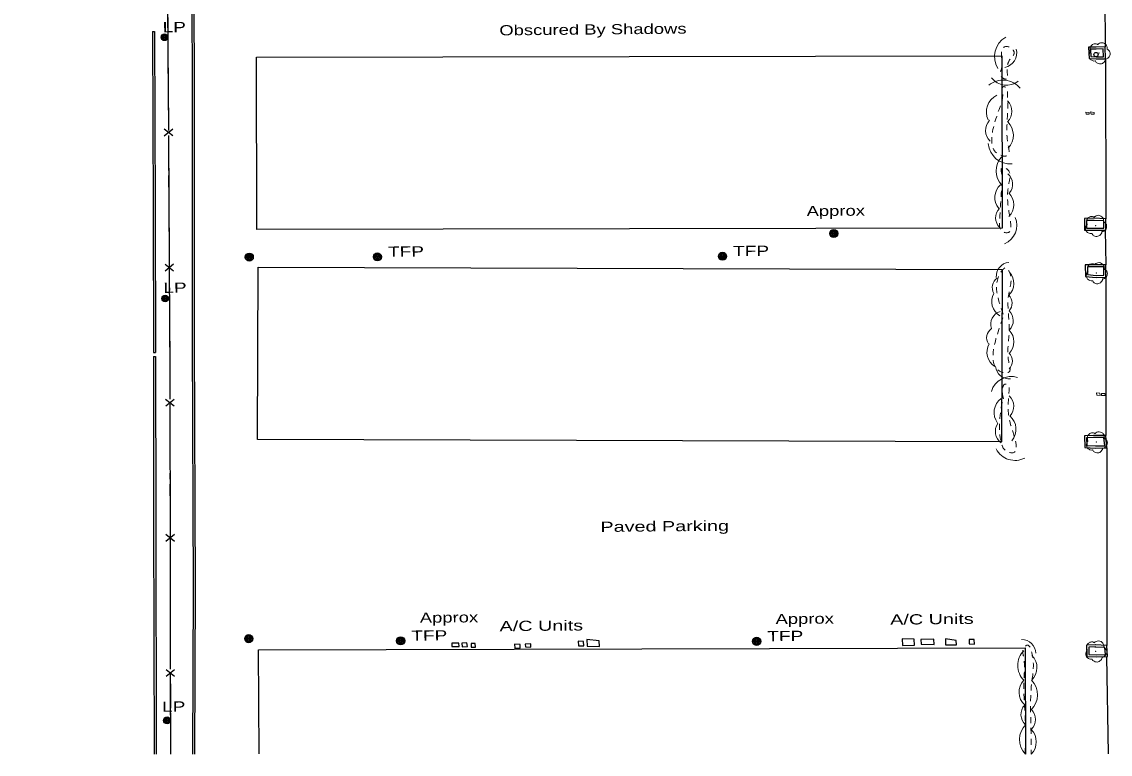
# Model space of a CAD drawing. Extents: x 2362213 to 2366494, y 6968794 to 6978110.
# Drawn here: x 2362436 to 2362949, y 6975890 to 6976234 of the extents above; entities that cross this region are included whole.
import ezdxf

# ---------------------------------------------------------------- set-up
doc = ezdxf.new("R2010")
doc.units = 0
doc.header["$LTSCALE"] = 1.9
doc.linetypes.add('LONG_DASH_SHORT_DASH', pattern=[9.9, 6, -1.2, 1.5, -1.2])
doc.linetypes.add('SHORT_DASHED', pattern=[2.7, 1.5, -1.2])
for name, color, linetype, lineweight in [('11', 7, 'Continuous', 25), ('17', 7, 'Continuous', 25), ('2', 7, 'Continuous', 25), ('20', 7, 'Continuous', 25), ('23', 7, 'Continuous', 25), ('29', 7, 'Continuous', 13), ('9', 7, 'Continuous', 13)]:
    doc.layers.add(name, color=color, linetype=linetype, lineweight=lineweight)

msp = doc.modelspace()

# ---------------------------------------------------------------- linework, layer by layer
at = {"layer": '11'}
for points in [[(2362546.8, 6976217.851), (2362897.792, 6976218.433), (2362897.925, 6976137.251), (2362546.933, 6976136.679)], [(2362547.593, 6976118.894), (2362897.85, 6976117.819), (2362897.601, 6976036.822), (2362547.344, 6976037.897)]]:
    msp.add_lwpolyline(points, close=True, dxfattribs=at)
msp.add_lwpolyline([(2362548.043, 6975889.887), (2362547.757, 6975938.867), (2362908.765, 6975939.844), (2362908.962, 6975889.735)], dxfattribs=at)
at = {"layer": '17'}
for p, q in [((2362503.4, 6976184.036), (2362507.411, 6976180.864)), ((2362503.411, 6976180.836), (2362507.4, 6976184.064)), ((2362505.393, 6976180.645), (2362505.744, 6976120.646)), ((2362503.776, 6976120.437), (2362507.797, 6976117.265)), ((2362503.797, 6976117.237), (2362507.777, 6976120.465)), ((2362504.082, 6976056.846), (2362508.093, 6976053.654)), ((2362504.092, 6976053.646), (2362508.083, 6976056.854)), ((2362506.054, 6976053.445), (2362506.155, 6975993.443)), ((2362504.197, 6975993.244), (2362508.199, 6975990.052)), ((2362504.198, 6975990.044), (2362508.198, 6975993.252)), ((2362506.16, 6975989.843), (2362506.271, 6975929.842)), ((2362504.303, 6975929.643), (2362508.314, 6975926.45)), ((2362504.313, 6975926.442), (2362508.304, 6975929.652)), ((2362506.275, 6975926.241), (2362506.343, 6975889.77))]:
    msp.add_line(p, q, dxfattribs=at)
at = {"layer": '17', "linetype": 'LONG_DASH_SHORT_DASH'}
msp.add_lwpolyline([(2362436.337, 6976448.61), (2362504.849, 6976448.732), (2362504.318, 6976368.123), (2362505.162, 6976218.565), (2362506.025, 6976073.326), (2362506.343, 6975889.77)], dxfattribs=at)
at = {"layer": '17'}
for points in [[(2362505.017, 6976244.244), (2362505.162, 6976218.565), (2362505.369, 6976184.245)], [(2362505.768, 6976117.046), (2362506.025, 6976073.326), (2362506.05, 6976057.045)]]:
    msp.add_lwpolyline(points, dxfattribs=at)
at = {"layer": '2'}
for p, q in [((2362945.945, 6976312.786), (2362946.463, 6976222.697)), ((2362497.914, 6976229.806), (2362498.874, 6976229.805)), ((2362946.578, 6976216.989), (2362946.745, 6976141.646)), ((2362946.476, 6976136.353), (2362946.771, 6976120.005)), ((2362946.776, 6976114.225), (2362946.686, 6976039.711)), ((2362498.302, 6976078.812), (2362499.262, 6976078.811)), ((2362498.41, 6976076.933), (2362499.37, 6976076.912)), ((2362947.251, 6976033.915), (2362947.167, 6975940.89)), ((2362947.117, 6975935.66), (2362947.752, 6975889.964))]:
    msp.add_line(p, q, dxfattribs=at)
for points in [[(2362516.903, 6975889.811), (2362517.148, 6975967.996), (2362516.689, 6976084.468), (2362516.713, 6976180.693), (2362516.548, 6976268.375), (2362510.238, 6976274.686)], [(2362517.863, 6975889.81), (2362518.108, 6975967.996), (2362517.649, 6976084.468), (2362517.673, 6976180.692), (2362517.504, 6976268.775), (2362510.911, 6976275.362)], [(2362497.914, 6976229.806), (2362498.239, 6976146.365), (2362498.302, 6976078.812)], [(2362498.874, 6976229.805), (2362499.199, 6976146.364), (2362499.262, 6976078.811)], [(2362942.115, 6976222.546), (2362938.534, 6976222.582), (2362938.806, 6976217.155), (2362942.117, 6976217.046)], [(2362942.104, 6976221.586), (2362939.543, 6976221.611), (2362939.717, 6976218.083), (2362942.148, 6976218.006)], [(2362942.117, 6976217.046), (2362946.578, 6976216.989), (2362946.463, 6976222.697), (2362942.115, 6976222.546)], [(2362942.128, 6976218.006), (2362945.598, 6976217.959), (2362945.523, 6976221.708), (2362942.144, 6976221.586)], [(2362941.172, 6976141.963), (2362936.612, 6976141.91), (2362936.714, 6976136.45), (2362946.706, 6976136.355), (2362946.786, 6976139.426)], [(2362941.181, 6976141.003), (2362937.591, 6976140.959), (2362937.655, 6976137.399), (2362945.766, 6976137.327), (2362945.826, 6976139.447)], [(2362945.826, 6976139.407), (2362945.804, 6976140.737), (2362940.881, 6976141)], [(2362946.786, 6976139.426), (2362946.745, 6976141.646), (2362940.932, 6976141.961)], [(2362941.901, 6976120.019), (2362937.061, 6976120.033), (2362937.162, 6976114.634), (2362942.117, 6976114.141)], [(2362941.9, 6976119.059), (2362938.04, 6976119.072), (2362938.104, 6976115.503), (2362942.208, 6976115.092)], [(2362942.098, 6976115.101), (2362945.817, 6976115.166), (2362945.81, 6976119.046), (2362941.9, 6976119.059)], [(2362942.117, 6976114.141), (2362946.776, 6976114.225), (2362946.771, 6976120.005), (2362941.901, 6976120.019)], [(2362498.41, 6976076.933), (2362498.431, 6976000.171), (2362498.662, 6975889.757)], [(2362499.37, 6976076.932), (2362499.391, 6976000.17), (2362499.622, 6975889.756)], [(2362940.976, 6976039.717), (2362936.706, 6976039.596), (2362936.809, 6976034.066), (2362941.861, 6976033.844)], [(2362941.005, 6976038.757), (2362937.685, 6976038.665), (2362937.75, 6976034.985), (2362941.902, 6976034.804)], [(2362941.852, 6976034.804), (2362946.192, 6976034.865), (2362945.815, 6976038.753), (2362940.975, 6976038.756)], [(2362941.861, 6976033.844), (2362947.251, 6976033.915), (2362946.686, 6976039.711), (2362940.976, 6976039.717)], [(2362941.904, 6975941.17), (2362937.695, 6975940.99), (2362937.826, 6975935.662), (2362942.528, 6975935.547)], [(2362942.528, 6975935.547), (2362947.577, 6975935.675), (2362947.167, 6975940.89), (2362941.654, 6975941.158)], [(2362941.943, 6975940.21), (2362938.674, 6975940.069), (2362938.767, 6975936.601), (2362942.548, 6975936.507)], [(2362942.498, 6975936.506), (2362946.538, 6975936.605), (2362946.276, 6975939.971), (2362941.603, 6975940.197)]]:
    msp.add_lwpolyline(points, dxfattribs=at)
at = {"layer": '20'}
for centre, radius in [((2362503.54, 6976227.17), 1.6), ((2362503.54, 6976227.17), 1.3), ((2362503.54, 6976227.17), 1), ((2362503.54, 6976227.17), 0.539), ((2362503.54, 6976227.17), 0.192), ((2362818.634, 6976134.806), 1.9), ((2362818.634, 6976134.806), 1.442), ((2362818.634, 6976134.806), 0.973), ((2362818.634, 6976134.806), 0.539), ((2362818.634, 6976134.806), 0.192), ((2362543.457, 6976123.695), 1.9), ((2362603.769, 6976123.819), 1.9), ((2362766.254, 6976124.106), 1.9), ((2362766.254, 6976124.106), 1.442), ((2362543.457, 6976123.695), 1.442), ((2362543.457, 6976123.695), 0.973), ((2362543.457, 6976123.695), 0.539), ((2362543.457, 6976123.695), 0.192), ((2362603.769, 6976123.819), 1.442), ((2362603.769, 6976123.819), 0.973), ((2362603.769, 6976123.819), 0.539), ((2362603.769, 6976123.819), 0.192), ((2362766.254, 6976124.106), 0.973), ((2362766.254, 6976124.106), 0.539), ((2362766.254, 6976124.106), 0.192), ((2362503.881, 6976104.217), 1.6), ((2362503.881, 6976104.217), 1.3), ((2362503.881, 6976104.217), 1), ((2362503.881, 6976104.217), 0.539), ((2362503.881, 6976104.217), 0.192), ((2362543.197, 6975944.114), 1.9), ((2362543.197, 6975944.114), 1.442), ((2362543.197, 6975944.114), 0.973), ((2362543.197, 6975944.114), 0.539), ((2362543.197, 6975944.114), 0.192), ((2362614.74, 6975943.095), 1.9), ((2362614.74, 6975943.095), 1.442), ((2362614.74, 6975943.095), 0.973), ((2362614.74, 6975943.095), 0.539), ((2362614.74, 6975943.095), 0.192), ((2362782.34, 6975942.851), 1.9), ((2362782.34, 6975942.851), 1.442), ((2362782.34, 6975942.851), 0.973), ((2362782.34, 6975942.851), 0.539), ((2362782.34, 6975942.851), 0.192), ((2362504.741, 6975905.666), 1.6), ((2362504.741, 6975905.666), 1.3), ((2362504.741, 6975905.666), 1), ((2362504.741, 6975905.666), 0.539), ((2362504.741, 6975905.666), 0.192)]:
    msp.add_circle(centre, radius, dxfattribs=at)
at = {"layer": '23'}
for points in [[(2362638.871, 6975941.984), (2362638.866, 6975940.454), (2362642.208, 6975940.376), (2362642.113, 6975941.945)], [(2362643.573, 6975941.939), (2362643.679, 6975940.27), (2362646.178, 6975940.384), (2362645.931, 6975942.152)], [(2362647.924, 6975941.881), (2362647.961, 6975940.041), (2362649.98, 6975940.11), (2362649.804, 6975941.778)], [(2362668.288, 6975941.534), (2362668.495, 6975939.726), (2362671.006, 6975939.71), (2362670.97, 6975941.34)], [(2362673.367, 6975941.523), (2362673.5, 6975940.204), (2362676.011, 6975940.078), (2362675.945, 6975941.747)], [(2362698.325, 6975942.971), (2362698.406, 6975940.711), (2362700.987, 6975940.686), (2362700.877, 6975942.745)], [(2362702.358, 6975943.669), (2362702.588, 6975940.551), (2362708.401, 6975940.416), (2362708.145, 6975943.084)], [(2362850.812, 6975944.043), (2362851.013, 6975940.884), (2362856.611, 6975941.088), (2362856.485, 6975943.837)], [(2362859.686, 6975943.657), (2362859.726, 6975941.467), (2362865.958, 6975941.407), (2362865.745, 6975943.875)], [(2362871.274, 6975943.977), (2362871.191, 6975941.157), (2362876.371, 6975941.186), (2362876.261, 6975943.275)], [(2362882.446, 6975943.704), (2362882.416, 6975941.613), (2362884.957, 6975941.588), (2362884.747, 6975943.746)]]:
    msp.add_lwpolyline(points, close=True, dxfattribs=at)
at = {"layer": '29', "lineweight": 25}
msp.add_circle((2362942.078, 6976219.025), 1, dxfattribs=at)
at = {"layer": '29'}
for centre in [(2362943.561, 6976219.749), (2362941.935, 6976138.53), (2362942.287, 6976116.262), (2362942.295, 6976036.639), (2362941.992, 6975938.211)]:
    msp.add_circle(centre, 0.1, dxfattribs=at)
for centre, radius, start, end in [((2362905.109, 6976218.042), 10.752, 120.96454, 210.96454), ((2362897.596, 6976219.915), 7.163, 283.30301, 13.30301), ((2362900.038, 6976213.566), 8.964, 217.30334, 307.30334), ((2362898.3, 6976196.53), 10.436, 39.42989, 129.42989), ((2362899.184, 6976192.016), 8.701, 115.38514, 205.38514), ((2362895.536, 6976192.253), 6.953, 315.05953, 45.05953), ((2362897.065, 6976183.288), 6.953, 136.51489, 226.51489), ((2362894.511, 6976181.026), 8.701, 316.2547, 46.2547), ((2362901.791, 6976177.929), 10.436, 184.41438, 274.41438), ((2362904.497, 6976164.242), 9.471, 135.10703, 225.10703), ((2362896.557, 6976158.061), 6.31, 319.41775, 49.41775), ((2362902.343, 6976151.754), 7.896, 130.59686, 220.59686), ((2362895.465, 6976148.291), 7.896, 315.40032, 45.40032), ((2362901.145, 6976142.19), 6.31, 135.9554, 225.9554), ((2362895.331, 6976138.663), 9.471, 293.36879, 23.36879), ((2362901.593, 6976114.757), 6.449, 95.23174, 185.23174), ((2362895.649, 6976111.348), 7.735, 312.98415, 42.98415), ((2362898.391, 6976109.396), 5.154, 122.26165, 212.26165), ((2362900.728, 6976102.758), 7.735, 150.01305, 240.01305), ((2362897.468, 6976102.042), 5.154, 316.0432, 46.0432), ((2362899.007, 6976092.033), 6.449, 107.68819, 197.68819), ((2362896.677, 6976093.829), 6.449, 315.65541, 45.65541), ((2362895.728, 6976085.764), 5.154, 123.82098, 213.82098), ((2362895.722, 6976083.859), 7.735, 314.88557, 44.88557), ((2362898.449, 6976078.885), 7.735, 149.11897, 239.11897), ((2362897.597, 6976074.813), 5.154, 314.77694, 44.77694), ((2362901.233, 6976072.859), 6.449, 185.26687, 275.26687), ((2362902.357, 6976057.572), 9.943, 73.31528, 163.31528), ((2362902.386, 6976050.525), 8.29, 126.49387, 216.49387), ((2362896.751, 6976053.481), 6.625, 317.51661, 47.51661), ((2362896.147, 6976042.634), 8.29, 319.83479, 49.83479), ((2362901.327, 6976041.643), 6.625, 144.79623, 234.79623), ((2362903.978, 6976037.958), 9.943, 207.29734, 297.29734), ((2362907.224, 6975937.101), 6.568, 1.26817, 91.26817), ((2362915.091, 6975931.54), 9.858, 135.39613, 225.39613), ((2362906.083, 6975930.43), 8.219, 314.44071, 44.44071), ((2362914.096, 6975918.94), 8.219, 137.24743, 227.24743), ((2362904.69, 6975917.658), 9.858, 314.46522, 44.46522), ((2362913.342, 6975908.414), 6.568, 137.2151, 227.2151), ((2362907.017, 6975906.098), 6.568, 314.53247, 44.53247), ((2362915.921, 6975896.591), 9.858, 134.07315, 224.07315), ((2362905.774, 6975895.59), 8.219, 314.847, 44.847)]:
    msp.add_arc(centre, radius, start, end, dxfattribs=at)
at = {"layer": '29', "linetype": 'SHORT_DASHED'}
for points in [[(2362897.91, 6976212.314), (2362897.626, 6976218.012), (2362897.583, 6976218.291), (2362897.566, 6976219.021), (2362898.554, 6976222.381), (2362901.784, 6976222.342), (2362903.579, 6976219.729), (2362901.647, 6976216.871), (2362900.359, 6976213.508), (2362900.529, 6976208.189), (2362900.534, 6976207.729), (2362898.272, 6976207.938), (2362897.793, 6976213.073)], [(2362897.873, 6976197.343), (2362898.072, 6976201.595), (2362897.936, 6976203.294), (2362898.241, 6976203.787), (2362899.563, 6976203.64), (2362900.447, 6976201.048), (2362900.436, 6976190.677), (2362900.742, 6976176.42), (2362900.556, 6976171.818), (2362899.93, 6976171.352), (2362897.95, 6976171.383), (2362898.08, 6976197.665)], [(2362898.002, 6976157.533), (2362897.761, 6976162.821), (2362897.715, 6976165.57), (2362900.089, 6976165.193), (2362901.017, 6976158.041), (2362901.047, 6976145.411), (2362902.015, 6976138.33), (2362901.411, 6976135.604), (2362898.14, 6976135.653), (2362896.72, 6976140.95), (2362897.76, 6976157.67)], [(2362898.449, 6976096.884), (2362898.091, 6976117.652), (2362899.362, 6976118.654), (2362901.026, 6976117.19), (2362901.018, 6976106.469), (2362901.27, 6976089.491), (2362901.223, 6976073.45), (2362901.228, 6976069.759), (2362899.674, 6976069.135), (2362898.382, 6976069.322), (2362898.733, 6976096.507)], [(2362898.509, 6976057.002), (2362898.461, 6976063.133), (2362898.805, 6976063.696), (2362900.154, 6976063.859), (2362901.129, 6976060.148), (2362901.758, 6976045.583), (2362902.821, 6976031.573), (2362899.138, 6976032.937), (2362897.548, 6976036.102), (2362898.159, 6976057.029)], [(2362908.752, 6975889.733), (2362908.821, 6975905.574), (2362908.133, 6975923.238), (2362908.007, 6975935.448), (2362908.106, 6975939.728), (2362909.753, 6975941.084), (2362911.94, 6975937.265), (2362911.796, 6975922.922), (2362911.567, 6975896.649), (2362911.562, 6975889.75)]]:
    msp.add_spline(points, degree=3, dxfattribs=at)
at = {"layer": '29'}
for points in [[(2362939.596, 6976220.322), (2362939.616, 6976220.332), (2362939.535, 6976220.401), (2362939.299, 6976221.029), (2362939.337, 6976222.309), (2362940.224, 6976223.608), (2362941.53, 6976224.09), (2362942.652, 6976223.901), (2362942.883, 6976223.773), (2362942.953, 6976223.774), (2362943.003, 6976223.814), (2362943.35, 6976224.108), (2362944.216, 6976224.556), (2362945.426, 6976224.487), (2362946.542, 6976223.898), (2362947.276, 6976222.475), (2362947.284, 6976221.615)], [(2362947.274, 6976221.635), (2362948.413, 6976220.576), (2362948.698, 6976218.988), (2362947.991, 6976217.662), (2362947.337, 6976217.116), (2362946.669, 6976216.9), (2362946.519, 6976216.888), (2362946.5, 6976216.778), (2362946.178, 6976215.875), (2362944.639, 6976214.709), (2362942.747, 6976214.992), (2362941.848, 6976215.934), (2362941.776, 6976216.063), (2362941.657, 6976216.042), (2362940.445, 6976216.161), (2362939.176, 6976217.158), (2362938.83, 6976218.794), (2362939.2, 6976219.818), (2362939.526, 6976220.261), (2362939.596, 6976220.312)], [(2362937.969, 6976139.102), (2362937.989, 6976139.113), (2362937.908, 6976139.182), (2362937.672, 6976139.81), (2362937.71, 6976141.09), (2362938.598, 6976142.389), (2362939.903, 6976142.871), (2362941.025, 6976142.682), (2362941.256, 6976142.554), (2362941.326, 6976142.555), (2362941.376, 6976142.595), (2362941.723, 6976142.888), (2362942.589, 6976143.337), (2362943.8, 6976143.268), (2362944.915, 6976142.679), (2362945.649, 6976141.256), (2362945.657, 6976140.396)], [(2362945.647, 6976140.416), (2362946.787, 6976139.356), (2362947.072, 6976137.769), (2362946.365, 6976136.442), (2362945.71, 6976135.896), (2362945.042, 6976135.68), (2362944.892, 6976135.668), (2362944.873, 6976135.558), (2362944.552, 6976134.655), (2362943.013, 6976133.49), (2362941.12, 6976133.772), (2362940.221, 6976134.714), (2362940.15, 6976134.843), (2362940.03, 6976134.822), (2362938.819, 6976134.94), (2362937.549, 6976135.938), (2362937.204, 6976137.575), (2362937.574, 6976138.599), (2362937.9, 6976139.042), (2362937.969, 6976139.092)], [(2362938.321, 6976116.835), (2362938.341, 6976116.845), (2362938.26, 6976116.914), (2362938.024, 6976117.542), (2362938.062, 6976118.822), (2362938.95, 6976120.121), (2362940.255, 6976120.603), (2362941.377, 6976120.414), (2362941.608, 6976120.286), (2362941.678, 6976120.287), (2362941.728, 6976120.327), (2362942.075, 6976120.621), (2362942.941, 6976121.069), (2362944.152, 6976121), (2362945.267, 6976120.411), (2362946.001, 6976118.988), (2362946.009, 6976118.128)], [(2362945.999, 6976118.148), (2362947.139, 6976117.089), (2362947.424, 6976115.501), (2362946.717, 6976114.175), (2362946.062, 6976113.628), (2362945.394, 6976113.412), (2362945.244, 6976113.401), (2362945.225, 6976113.29), (2362944.904, 6976112.387), (2362943.365, 6976111.223), (2362941.472, 6976111.505), (2362940.573, 6976112.446), (2362940.502, 6976112.575), (2362940.382, 6976112.554), (2362939.171, 6976112.673), (2362937.901, 6976113.671), (2362937.556, 6976115.307), (2362937.926, 6976116.331), (2362938.252, 6976116.774), (2362938.321, 6976116.825)], [(2362946.007, 6976038.524), (2362947.147, 6976037.464), (2362947.432, 6976035.877), (2362946.725, 6976034.55), (2362946.07, 6976034.004), (2362945.402, 6976033.787), (2362945.252, 6976033.776), (2362945.233, 6976033.666), (2362944.912, 6976032.763), (2362943.373, 6976031.599), (2362941.48, 6976031.881), (2362940.581, 6976032.821), (2362940.51, 6976032.951), (2362940.39, 6976032.93), (2362939.179, 6976033.048), (2362937.909, 6976034.046), (2362937.564, 6976035.683), (2362937.934, 6976036.706), (2362938.26, 6976037.15), (2362938.329, 6976037.2)], [(2362938.329, 6976037.21), (2362938.349, 6976037.22), (2362938.269, 6976037.29), (2362938.033, 6976037.918), (2362938.07, 6976039.199), (2362938.958, 6976040.497), (2362940.263, 6976040.98), (2362941.385, 6976040.791), (2362941.617, 6976040.663), (2362941.687, 6976040.663), (2362941.736, 6976040.704), (2362942.083, 6976040.997), (2362942.949, 6976041.445), (2362944.16, 6976041.377), (2362945.276, 6976040.788), (2362946.009, 6976039.364), (2362946.017, 6976038.505)], [(2362938.027, 6975938.784), (2362938.046, 6975938.794), (2362937.966, 6975938.863), (2362937.73, 6975939.49), (2362937.768, 6975940.771), (2362938.655, 6975942.069), (2362939.961, 6975942.551), (2362941.083, 6975942.362), (2362941.314, 6975942.234), (2362941.384, 6975942.235), (2362941.433, 6975942.275), (2362941.781, 6975942.569), (2362942.646, 6975943.017), (2362943.857, 6975942.949), (2362944.973, 6975942.359), (2362945.706, 6975940.936), (2362945.715, 6975940.076)], [(2362945.704, 6975940.096), (2362946.844, 6975939.038), (2362947.13, 6975937.451), (2362946.422, 6975936.124), (2362945.767, 6975935.577), (2362945.099, 6975935.361), (2362944.95, 6975935.35), (2362944.931, 6975935.239), (2362944.609, 6975934.336), (2362943.07, 6975933.172), (2362941.177, 6975933.454), (2362940.278, 6975934.395), (2362940.207, 6975934.524), (2362940.087, 6975934.503), (2362938.876, 6975934.622), (2362937.607, 6975935.62), (2362937.261, 6975937.257), (2362937.631, 6975938.28), (2362937.957, 6975938.723), (2362938.027, 6975938.774)]]:
    msp.add_spline(points, degree=3, dxfattribs=at)
at = {"layer": '9'}
for points in [[(2362937.376, 6976191.969), (2362937.425, 6976190.96), (2362938.816, 6976190.913), (2362938.808, 6976191.753)], [(2362939.525, 6976192.04), (2362939.756, 6976190.902), (2362941.286, 6976190.926), (2362941.208, 6976191.766)], [(2362942.304, 6976059.819), (2362942.434, 6976058.77), (2362943.996, 6976058.625), (2362943.906, 6976059.674)], [(2362944.747, 6976059.582), (2362944.725, 6976058.642), (2362946.396, 6976058.638), (2362946.278, 6976059.477)]]:
    msp.add_lwpolyline(points, close=True, dxfattribs=at)

# ---------------------------------------------------------------- texts
at = {"layer": '2', "width": 1.45}
msp.add_text('Paved Parking', height=4.8, rotation=0.546, dxfattribs=at).set_placement((2362708.807, 6975994.344))
at = {"layer": '20'}
for s, width, p in [('  LP', 1.4, (2362497.668, 6976229.434)), ('Obscured By Shadows', 1.35, (2362661.199, 6976228.041)), ('Approx', 1.35, (2362805.866, 6976142.975)), ('  TFP', 1.4, (2362603.768, 6976123.818)), ('  TFP', 1.4, (2362766.253, 6976124.106)), ('  LP', 1.4, (2362498.006, 6976106.811)), ('Approx', 1.35, (2362623.76, 6975951.582)), ('Approx', 1.35, (2362791.243, 6975950.967)), ('  TFP', 1.4, (2362614.74, 6975943.095)), ('  TFP', 1.4, (2362782.341, 6975942.851)), ('  LP', 1.4, (2362497.423, 6975909.677))]:
    msp.add_text(s, height=4.8, rotation=0.546, dxfattribs=dict(at, width=width)).set_placement(p)
at = {"layer": '23', "width": 1.45}
for p in [(2362661.329, 6975947.628), (2362845.229, 6975950.711)]:
    msp.add_text('A/C Units', height=4.8, rotation=0.546, dxfattribs=at).set_placement(p)

doc.saveas('drawing.dxf')
